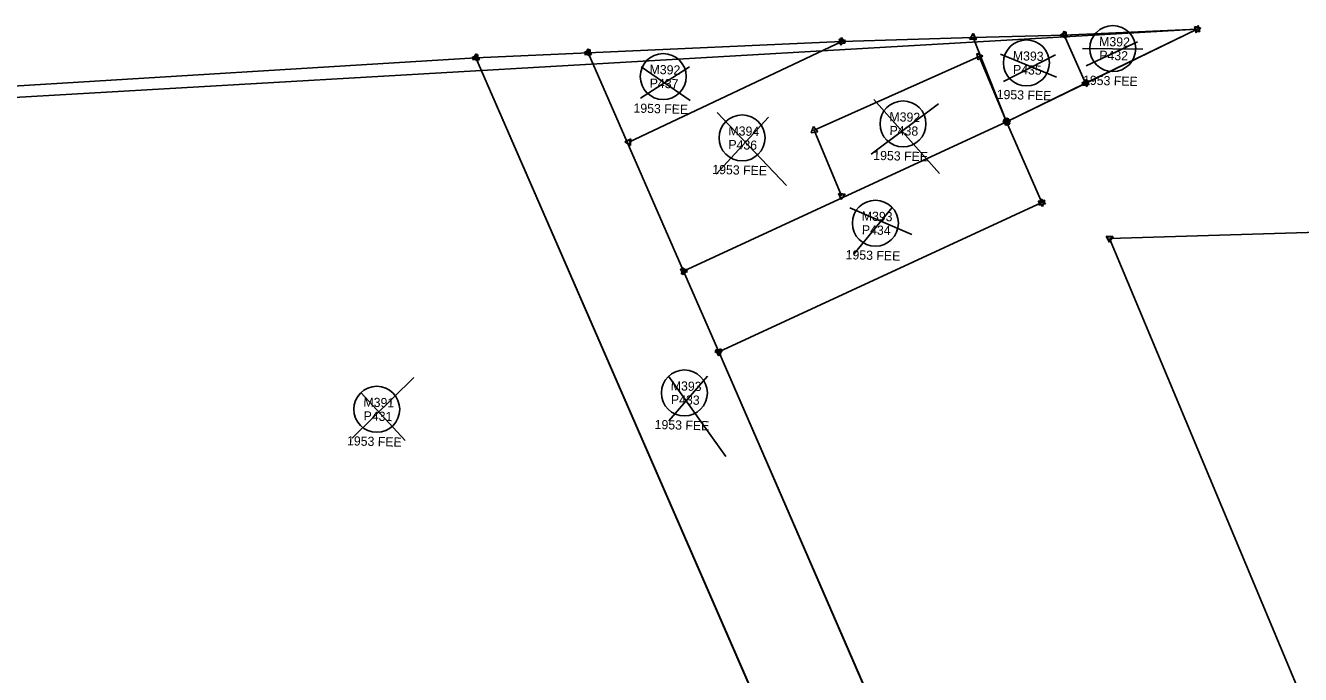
# Model space of a CAD drawing. Extents: x 325029 to 414988, y 1517527 to 1550420.
# Drawn here: x 359377 to 360105, y 1524933 to 1525304 of the extents above; entities that cross this region are included whole.
import ezdxf

# ---------------------------------------------------------------- set-up
doc = ezdxf.new("R2010")
doc.units = 0
for name, color, linetype in [('Level 56', 7, 'Continuous'), ('MHB', 7, 'Continuous'), ('MPL', 7, 'Continuous'), ('MRBL2', 7, 'Continuous'), ('MRBL3', 7, 'Continuous'), ('S_C', 7, 'Continuous')]:
    doc.layers.add(name, color=color, linetype=linetype)

msp = doc.modelspace()

# ---------------------------------------------------------------- linework, layer by layer
at = {"layer": 'Level 56'}
for centre in [(359997.57, 1525290.4), (359948.29, 1525282.24), (359740.94, 1525274.44), (359877.84, 1525247.44), (359785.96, 1525239.41), (359862.06, 1525190.72), (359753.03, 1525093.78), (359577.44, 1525084.44)]:
    msp.add_circle(centre, 13.12, dxfattribs=at)
at = {"layer": 'MHB'}
for p, q in [((359969.84, 1525298.13), (360045.76, 1525301.5)), ((360045.76, 1525301.5), (359982.07, 1525270.64)), ((359698.02, 1525288.06), (359842.88, 1525294.49)), ((359842.88, 1525294.49), (359721.3, 1525237.04)), ((359842.88, 1525294.49), (359917.85, 1525296.82)), ((359917.85, 1525296.82), (359969.84, 1525298.13)), ((359937, 1525248.62), (359917.85, 1525296.82)), ((359969.84, 1525298.13), (359982.07, 1525270.64)), ((358564.93, 1525219.75), (359634.08, 1525285.22)), ((359634.08, 1525285.22), (359698.02, 1525288.06)), ((359634.08, 1525285.22), (359815.77, 1524867.87)), ((359820.21, 1524858.06), (359634.08, 1525285.22)), ((359698.02, 1525288.06), (359752.6, 1525163.36)), ((359921.33, 1525285.96), (359827.11, 1525243.74)), ((359937, 1525248.62), (359921.33, 1525285.96)), ((359982.07, 1525270.64), (359937, 1525248.62)), ((359752.6, 1525163.36), (359937, 1525248.62)), ((359937, 1525248.62), (359957.07, 1525202.47)), ((359827.11, 1525243.74), (359842.78, 1525206.4)), ((359957.07, 1525202.47), (359772.67, 1525117.2)), ((359752.6, 1525163.36), (359772.67, 1525117.2)), ((359772.67, 1525117.2), (359884.14, 1524860.9))]:
    msp.add_line(p, q, dxfattribs=at)
for points in [[(359915.82, 1525296.01), (359918.16, 1525298.98)], [(359915.98, 1525295.68), (359917.79, 1525299)], [(359915.99, 1525295.67), (359917.78, 1525299)], [(359917.78, 1525299), (359919.77, 1525295.78)], [(359917.79, 1525299), (359919.76, 1525295.77)], [(359918.16, 1525298.98), (359919.56, 1525295.47)], [(359967.66, 1525298.21), (359971, 1525299.97)], [(359968, 1525296.95), (359969.74, 1525300.3)], [(359969.74, 1525300.3), (359971.78, 1525297.12)], [(359971, 1525299.97), (359970.85, 1525296.19)], [(360044.24, 1525303.06), (360047.88, 1525302.03)], [(360045.17, 1525299.4), (360044.24, 1525303.06)], [(360047.88, 1525302.03), (360045.17, 1525299.4)], [(359841.02, 1525293.34), (359842.81, 1525296.67)], [(359844.8, 1525293.46), (359841.02, 1525293.34)], [(359841.36, 1525296.06), (359844.99, 1525295.02)], [(359842.27, 1525292.4), (359841.36, 1525296.06)], [(359844.99, 1525295.02), (359842.27, 1525292.4)], [(359842.81, 1525296.67), (359844.8, 1525293.46)], [(359919.56, 1525295.47), (359915.82, 1525296.01)], [(359919.76, 1525295.77), (359915.98, 1525295.68)], [(359919.77, 1525295.78), (359915.99, 1525295.67)], [(359970.85, 1525296.19), (359967.66, 1525298.21)], [(359971.78, 1525297.12), (359968, 1525296.95)], [(359631.9, 1525285.28), (359635.22, 1525287.08)], [(359635.12, 1525283.31), (359631.9, 1525285.28)], [(359632.08, 1525284.35), (359634.33, 1525287.39)], [(359635.84, 1525283.93), (359632.08, 1525284.35)], [(359632.24, 1525284.05), (359633.98, 1525287.4)], [(359636.02, 1525284.22), (359632.24, 1525284.05)], [(359633.98, 1525287.4), (359636.02, 1525284.22)], [(359634.33, 1525287.39), (359635.84, 1525283.93)], [(359635.22, 1525287.08), (359635.12, 1525283.31)], [(359695.84, 1525288.13), (359699.17, 1525289.91)], [(359699.04, 1525286.14), (359695.84, 1525288.13)], [(359696.18, 1525286.89), (359697.92, 1525290.24)], [(359699.95, 1525287.05), (359696.18, 1525286.89)], [(359697.92, 1525290.24), (359699.95, 1525287.05)], [(359699.17, 1525289.91), (359699.04, 1525286.14)], [(359920.53, 1525283.94), (359919.98, 1525287.67)], [(359919.98, 1525287.67), (359923.49, 1525286.29)], [(359923.49, 1525286.29), (359920.53, 1525283.94)], [(359979.89, 1525270.8), (359983.29, 1525272.45)], [(359983.02, 1525268.68), (359979.89, 1525270.8)], [(359980.4, 1525269.24), (359981.69, 1525272.79)], [(359984.12, 1525269.9), (359980.4, 1525269.24)], [(359981.69, 1525272.79), (359984.12, 1525269.9)], [(359983.29, 1525272.45), (359983.02, 1525268.68)], [(359934.85, 1525248.27), (359937.78, 1525250.66)], [(359938.38, 1525246.93), (359934.85, 1525248.27)], [(359934.99, 1525247.78), (359937.28, 1525250.79)], [(359938.74, 1525247.3), (359934.99, 1525247.78)], [(359936.22, 1525246.59), (359935.63, 1525250.32)], [(359935.63, 1525250.32), (359939.16, 1525248.96)], [(359939.16, 1525248.96), (359936.22, 1525246.59)], [(359937.28, 1525250.79), (359938.74, 1525247.3)], [(359937.78, 1525250.66), (359938.38, 1525246.93)], [(359825.4, 1525242.39), (359826.79, 1525245.9)], [(359829.14, 1525242.94), (359825.4, 1525242.39)], [(359826.79, 1525245.9), (359829.14, 1525242.94)], [(359719.13, 1525237.23), (359722.54, 1525238.84)], [(359722.23, 1525235.08), (359719.13, 1525237.23)], [(359722.54, 1525238.84), (359722.23, 1525235.08)], [(359841.04, 1525207.72), (359844.79, 1525207.24)], [(359842.5, 1525204.24), (359841.04, 1525207.72)], [(359844.79, 1525207.24), (359842.5, 1525204.24)], [(359955.37, 1525201.09), (359956.72, 1525204.62)], [(359956.72, 1525204.62), (359959.1, 1525201.69)], [(359959.1, 1525201.69), (359955.37, 1525201.09)], [(359750.84, 1525164.65), (359754.6, 1525164.23)], [(359752.35, 1525161.19), (359750.84, 1525164.65)], [(359751.35, 1525161.57), (359751.69, 1525165.34)], [(359754.78, 1525163.16), (359751.35, 1525161.57)], [(359751.69, 1525165.34), (359754.78, 1525163.16)], [(359754.6, 1525164.23), (359752.35, 1525161.19)], [(359770.49, 1525117.4), (359773.92, 1525118.99)], [(359773.58, 1525115.23), (359770.49, 1525117.4)], [(359770.91, 1525118.5), (359774.66, 1525118.07)], [(359772.42, 1525115.04), (359770.91, 1525118.5)], [(359774.66, 1525118.07), (359772.42, 1525115.04)], [(359773.92, 1525118.99), (359773.58, 1525115.23)]]:
    msp.add_lwpolyline(points, dxfattribs=at)
for centre, radius in [((359969.84, 1525298.13), 1.09), ((359969.84, 1525298.13), 0.227), ((360045.76, 1525301.5), 0.227), ((359842.88, 1525294.49), 1.09), ((359842.88, 1525294.49), 0.227), ((359917.85, 1525296.82), 1.09), ((359917.85, 1525296.82), 1.09), ((359917.85, 1525296.82), 1.09), ((359634.08, 1525285.23), 1.09), ((359634.08, 1525285.22), 1.09), ((359634.08, 1525285.22), 0.227), ((359698.02, 1525288.06), 1.09), ((359698.02, 1525288.06), 0.227), ((359921.33, 1525285.96), 0.227), ((359982.07, 1525270.64), 1.09), ((359982.07, 1525270.64), 0.227), ((359937, 1525248.62), 1.09), ((359937, 1525248.62), 0.227), ((359937, 1525248.62), 0.227), ((359827.11, 1525243.74), 0.227), ((359721.3, 1525237.04), 1.09), ((359842.78, 1525206.4), 1.09), ((359957.07, 1525202.47), 0.227), ((359752.6, 1525163.36), 1.09), ((359752.6, 1525163.36), 0.227), ((359772.67, 1525117.2), 1.09), ((359772.67, 1525117.2), 0.227)]:
    msp.add_circle(centre, radius, dxfattribs=at)
at = {"layer": 'MPL'}
for p, q in [((360045.76, 1525301.5), (358029.95, 1525185)), ((359937, 1525248.62), (360045.76, 1525301.5)), ((359862.94, 1524910), (359772.67, 1525117.2))]:
    msp.add_line(p, q, dxfattribs=at)
for points in [[(360043.66, 1525300.95), (360046.35, 1525303.6)], [(360047.3, 1525299.94), (360043.66, 1525300.95)], [(360046.35, 1525303.6), (360047.3, 1525299.94)], [(359934.96, 1525249.38), (359938.68, 1525250.01)], [(359937.37, 1525246.47), (359934.96, 1525249.38)], [(359938.68, 1525250.01), (359937.37, 1525246.47)], [(359955.03, 1525203.24), (359958.76, 1525203.84)], [(359958.76, 1525203.84), (359957.42, 1525200.31)], [(359957.42, 1525200.31), (359955.03, 1525203.24)], [(359770.63, 1525117.98), (359774.36, 1525118.58)], [(359773.02, 1525115.05), (359770.63, 1525117.98)], [(359774.36, 1525118.58), (359773.02, 1525115.05)]]:
    msp.add_lwpolyline(points, dxfattribs=at)
for centre in [(360045.76, 1525301.5), (359937, 1525248.62), (359957.07, 1525202.47), (359772.67, 1525117.2)]:
    msp.add_circle(centre, 0.227, dxfattribs=at)
at = {"layer": 'MRBL2'}
msp.add_line((360491.49, 1525197.03), (359995.71, 1525182.03), dxfattribs=at)
for points in [[(359993.79, 1525183.06), (359997.57, 1525183.18)], [(359995.78, 1525179.85), (359993.79, 1525183.06)], [(359997.57, 1525183.18), (359995.78, 1525179.85)]]:
    msp.add_lwpolyline(points, dxfattribs=at)
msp.add_circle((359995.71, 1525182.03), 1.09, dxfattribs=at)
at = {"layer": 'MRBL3'}
msp.add_line((359995.71, 1525182.03), (360154.03, 1524803.87), dxfattribs=at)
for points in [[(359993.98, 1525183.35), (359997.72, 1525182.87)], [(359995.44, 1525179.86), (359993.98, 1525183.35)], [(359997.72, 1525182.87), (359995.44, 1525179.86)]]:
    msp.add_lwpolyline(points, dxfattribs=at)
msp.add_circle((359995.72, 1525182.03), 1.09, dxfattribs=at)
at = {"layer": 'S_C'}
for p, q in [((360011.77, 1525294.35), (359982.46, 1525280.64)), ((359933.52, 1525287.14), (359965.39, 1525274.14)), ((359964.85, 1525286.82), (359935.2, 1525271.61)), ((359980.39, 1525290.5), (360014.72, 1525290.16)), ((359755.89, 1525280.06), (359728.04, 1525262.17)), ((359728.37, 1525279.96), (359756.35, 1525260.84)), ((359898.14, 1525258.89), (359859.57, 1525230.16)), ((359861.27, 1525261.41), (359898.61, 1525219.15)), ((359801.07, 1525251.18), (359771.14, 1525218.8)), ((359771.78, 1525254.01), (359811.36, 1525212.25)), ((359847.57, 1525199.55), (359882.92, 1525184.35)), ((359871.58, 1525199.76), (359849.8, 1525173.06)), ((359598.64, 1525102.53), (359563.45, 1525068.03)), ((359744, 1525103.3), (359776.73, 1525057.57)), ((359766.14, 1525103.39), (359744.21, 1525077.77)), ((359568.41, 1525093.96), (359593.7, 1525066.57))]:
    msp.add_line(p, q, dxfattribs=at)

# ---------------------------------------------------------------- texts
at = {"layer": 'Level 56'}
for s, p in [('M392', (359989.73, 1525291.92)), ('M393', (359940.47, 1525283.76)), ('P432', (359989.82, 1525284.04)), ('M392', (359733.1, 1525275.96)), ('P435', (359940.54, 1525275.88)), ('P437', (359733.18, 1525268.09)), ('1953 FEE', (359980.54, 1525269.83)), ('1953 FEE', (359931.26, 1525261.67)), ('1953 FEE', (359723.91, 1525253.87)), ('M392', (359870, 1525248.96)), ('M394', (359778.11, 1525240.93)), ('P438', (359870.08, 1525241.08)), ('P436', (359778.08, 1525233.05)), ('1953 FEE', (359860.81, 1525226.87)), ('1953 FEE', (359768.92, 1525218.84)), ('M393', (359854.23, 1525192.24)), ('P434', (359854.3, 1525184.36)), ('1953 FEE', (359845.02, 1525170.15)), ('M393', (359745.21, 1525095.3)), ('M391', (359569.77, 1525085.96)), ('P433', (359745.3, 1525087.42)), ('P431', (359569.86, 1525078.08)), ('1953 FEE', (359736, 1525073.2)), ('1953 FEE', (359560.4, 1525063.87))]:
    msp.add_text(s, height=5.249, rotation=358.49067, dxfattribs=at).set_placement(p)

doc.saveas('drawing.dxf')
